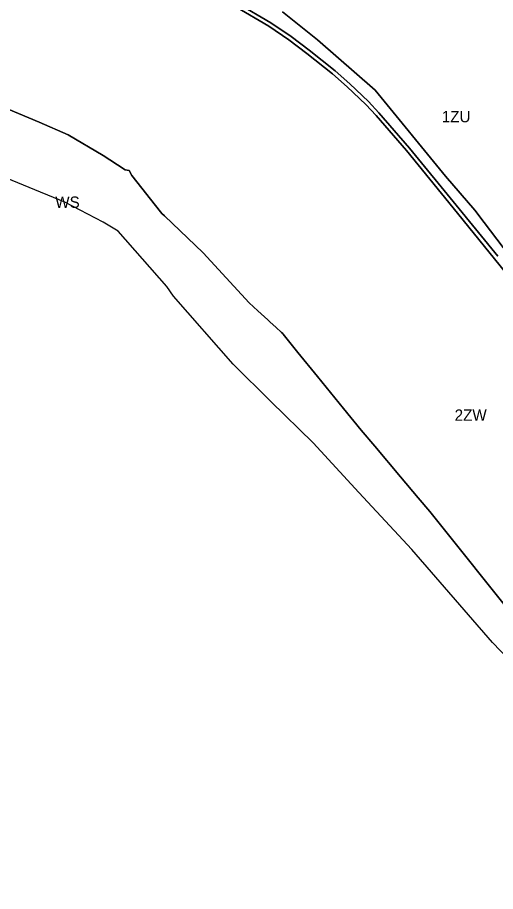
# Model space of a CAD drawing. Extents: x 7417411 to 7420955, y 5545251 to 5546537.
# Drawn here: x 7419153 to 7419574, y 5545252 to 5546021 of the extents above; entities that cross this region are included whole.
import ezdxf

# ---------------------------------------------------------------- set-up
doc = ezdxf.new("R2010")
doc.units = 0
doc.layers.add('linie_rozgraniczajace', color=7, linetype='Continuous')
doc.layers.add('oznaczenia_przeznaczen', color=7, linetype='Continuous')

msp = doc.modelspace()

# ---------------------------------------------------------------- linework, layer by layer
at = {"layer": 'linie_rozgraniczajace'}
for points in [[(7419576.04, 5545811.27), (7419539.44, 5545856.07), (7419498.31, 5545906.41), (7419471.51, 5545937.52), (7419462.36, 5545947.34), (7419445.84, 5545962.83), (7419432.93, 5545974.31), (7419410.07, 5545992.52), (7419394.32, 5546004.64), (7419376.35, 5546016.64), (7419347.1, 5546033.75)], [(7419347.1, 5546033.75), (7419376.35, 5546016.64), (7419394.32, 5546004.64), (7419410.07, 5545992.52), (7419432.93, 5545974.31), (7419445.84, 5545962.83), (7419462.36, 5545947.34), (7419471.51, 5545937.52), (7419498.31, 5545906.41), (7419539.44, 5545856.07), (7419576.04, 5545811.27)], [(7419345.39, 5546030.7), (7419374.5, 5546013.67), (7419392.28, 5546001.8), (7419407.91, 5545989.77), (7419430.68, 5545971.63), (7419443.48, 5545960.24), (7419459.88, 5545944.87), (7419468.9, 5545935.18), (7419495.63, 5545904.16), (7419536.73, 5545853.86), (7419573.33, 5545809.06), (7419595.63, 5545781.39)], [(7419595.63, 5545781.39), (7419573.33, 5545809.06), (7419536.73, 5545853.86), (7419495.63, 5545904.16), (7419468.9, 5545935.18), (7419459.88, 5545944.87), (7419443.48, 5545960.24), (7419430.68, 5545971.63), (7419407.91, 5545989.77), (7419392.28, 5546001.8), (7419374.5, 5546013.67), (7419345.39, 5546030.7)], [(7419591.92, 5545804.1), (7419564.22, 5545841.04), (7419555.83, 5545851.81), (7419530.14, 5545881.81), (7419468.15, 5545957.47), (7419417.45, 5546001.67), (7419386.66, 5546026.21)], [(7419386.66, 5546026.21), (7419417.45, 5546001.67), (7419468.15, 5545957.47), (7419530.14, 5545881.81), (7419555.83, 5545851.81), (7419564.22, 5545841.04), (7419591.92, 5545804.1)], [(7419145.1, 5545940.51), (7419172.19, 5545929.25), (7419197.75, 5545918.11), (7419228.68, 5545899.91), (7419234.57, 5545896.04), (7419248.07, 5545887.18), (7419251.59, 5545886.56), (7419253.91, 5545882.35), (7419279.06, 5545850.18), (7419280.43, 5545848.71)], [(7419643.4, 5545427.59), (7419538.5, 5545558.64), (7419516.15, 5545586.56), (7419506.06, 5545598.7), (7419490.35, 5545617.19), (7419467.79, 5545643.99), (7419455.92, 5545658.08), (7419440.25, 5545677.15), (7419417.3, 5545705.34), (7419400.01, 5545726.56), (7419393.01, 5545735.38), (7419387.19, 5545742.71), (7419386.79, 5545743.22), (7419385.77, 5545744.11), (7419380.66, 5545748.77), (7419375.74, 5545753.27), (7419373.6, 5545755.21), (7419364.98, 5545763.08), (7419357.34, 5545770.24), (7419316.59, 5545814.13), (7419282.75, 5545846.81), (7419280.43, 5545848.71), (7419279.06, 5545850.18), (7419253.91, 5545882.35), (7419251.59, 5545886.56), (7419248.07, 5545887.18), (7419234.57, 5545896.04), (7419228.68, 5545899.91), (7419197.75, 5545918.11), (7419172.19, 5545929.25), (7419145.1, 5545940.51)], [(7420258.68, 5545252.15), (7420092.31, 5545255.64), (7420001.57, 5545271.49), (7419978.39, 5545275.32), (7419915.42, 5545281.02), (7419848.54, 5545298.42), (7419811.72, 5545307.45), (7419738.09, 5545326.91), (7419682.01, 5545370.56), (7419636.59, 5545403.58), (7419571.38, 5545471.15), (7419500.52, 5545553.16), (7419453.87, 5545603.37), (7419413.65, 5545646.88), (7419376.29, 5545683.4), (7419343.05, 5545716.25), (7419290.63, 5545776.17), (7419284.76, 5545784.57), (7419241.76, 5545833.26), (7419228.74, 5545841.09), (7419194.92, 5545858.79), (7419126.7, 5545886.6)], [(7419280.43, 5545848.71), (7419282.75, 5545846.81), (7419316.59, 5545814.13), (7419357.34, 5545770.24), (7419364.98, 5545763.08), (7419373.6, 5545755.21), (7419375.74, 5545753.27), (7419380.66, 5545748.77), (7419385.77, 5545744.11), (7419386.79, 5545743.22), (7419387.19, 5545742.71), (7419393.01, 5545735.38), (7419400.01, 5545726.56), (7419417.3, 5545705.34), (7419440.25, 5545677.15), (7419455.92, 5545658.08), (7419467.79, 5545643.99), (7419490.35, 5545617.19), (7419506.06, 5545598.7), (7419516.15, 5545586.56), (7419538.5, 5545558.64), (7419643.4, 5545427.59)]]:
    msp.add_lwpolyline(points, dxfattribs=at)

# ---------------------------------------------------------------- texts
at = {"layer": 'oznaczenia_przeznaczen'}
for s, p in [('1ZU', (7419526.82, 5545929.09)), ('WS', (7419186.47, 5545853.79)), ('2ZW', (7419538.16, 5545666.42))]:
    msp.add_text(s, height=10, dxfattribs=at).set_placement(p)

doc.saveas('drawing.dxf')
